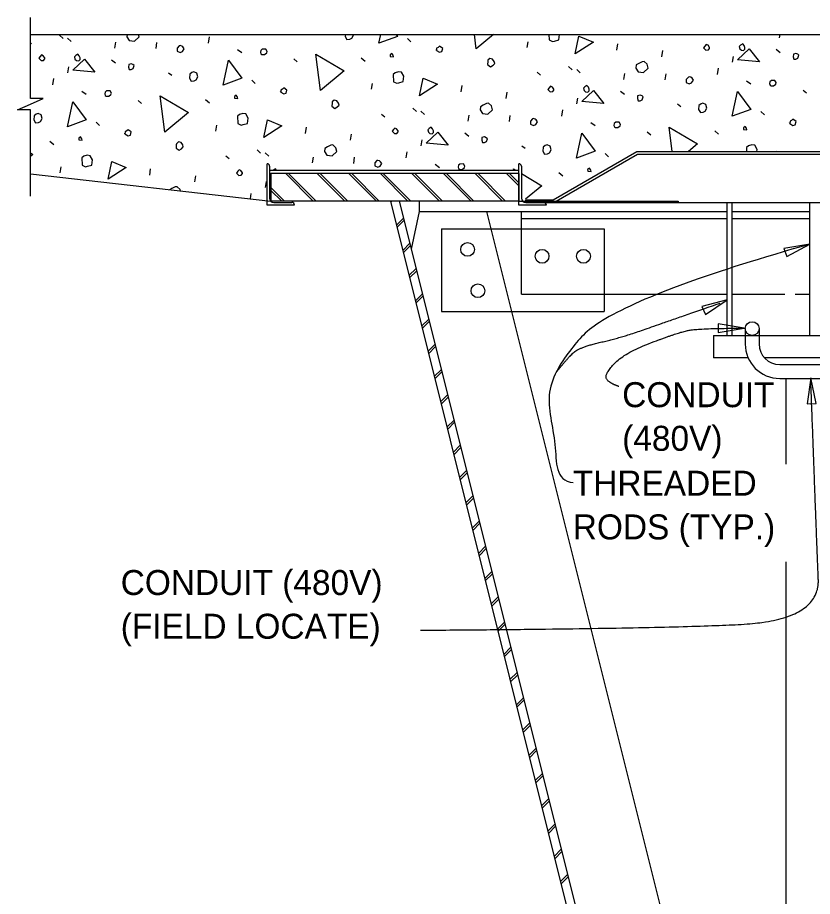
# Model space of a CAD drawing. Extents: x 927736.2 to 927809.6, y 636703.6 to 636757.7.
# Drawn here: x 927752.87 to 927764.73, y 636743.33 to 636756.45 of the extents above; entities that cross this region are included whole.
import ezdxf

# ---------------------------------------------------------------- set-up
doc = ezdxf.new("R2010")
doc.units = 0
for name, color, linetype in [('Default', 7, 'Continuous'), ('DimLines_dp', 7, 'Continuous'), ('Miscellaneous1', 7, 'Continuous'), ('Miscellaneous2', 7, 'Continuous'), ('Miscellaneous3', 7, 'Continuous')]:
    doc.layers.add(name, color=color, linetype=linetype)

msp = doc.modelspace()

# ---------------------------------------------------------------- linework, layer by layer
at = {"layer": 'Default'}
msp.add_line((927758.438, 636753.691), (927758.453, 636753.706), dxfattribs=at)
at = {"layer": 'DimLines_dp'}
msp.add_lwpolyline([(927753.063, 636753.782), (927753.063, 636755.07), (927752.871, 636755.07), (927753.063, 636755.153), (927753.254, 636755.237), (927753.063, 636755.237), (927753.063, 636756.446)], dxfattribs=at)
for points in [[(927764.692, 636753.067), (927764.306, 636753.003), (927764.349, 636752.88)], [(927763.458, 636752.234), (927763.081, 636752.133), (927763.135, 636752.014)], [(927763.711, 636751.811), (927763.325, 636751.876), (927763.325, 636751.746)], [(927764.705, 636751.071), (927764.654, 636750.684), (927764.785, 636750.688)]]:
    msp.add_lwpolyline(points, close=True, dxfattribs=at)
for points, degree in [([(927764.692, 636753.067), (927763.962, 636752.853), (927762.754, 636752.488), (927761.495, 636751.921), (927761.155, 636751.556), (927760.689, 636750.876), (927760.946, 636750.081), (927760.886, 636749.533), (927761.163, 636749.508)], 3), ([(927760.903, 636751.146), (927761.067, 636751.354), (927761.256, 636751.531), (927761.873, 636751.669), (927762.515, 636751.896), (927763.355, 636752.186)], 2), ([(927761.841, 636750.942), (927761.696, 636750.992), (927761.621, 636751.118), (927761.929, 636751.446), (927762.729, 636751.748), (927763.037, 636751.811), (927763.711, 636751.811)], 2), ([(927758.883, 636747.305), (927762.516, 636747.33), (927764.844, 636747.456), (927764.793, 636748.678), (927764.705, 636751.071)], 2)]:
    msp.add_open_spline(points, degree=degree, dxfattribs=at)
at = {"layer": 'Miscellaneous1'}
for p, q in [((927763.728, 636751.805), (927763.728, 636751.575)), ((927763.934, 636751.805), (927763.934, 636751.576)), ((927763.253, 636751.702), (927763.253, 636751.368)), ((927763.253, 636751.702), (927764.974, 636751.702)), ((927763.772, 636751.368), (927763.253, 636751.368)), ((927764.974, 636751.368), (927764.014, 636751.368)), ((927765.497, 636751.267), (927764.242, 636751.267)), ((927764.242, 636751.062), (927765.497, 636751.061))]:
    msp.add_line(p, q, dxfattribs=at)
msp.add_circle((927763.831, 636751.805), 0.103, dxfattribs=at)
for centre, radius in [((927764.242, 636751.575), 0.514), ((927764.242, 636751.576), 0.308)]:
    msp.add_arc(centre, radius, 180, 269.9792, dxfattribs=at)
at = {"layer": 'Miscellaneous2'}
for p, q in [((927753.063, 636756.193), (927774, 636756.193)), ((927753.498, 636756.185), (927753.55, 636756.135)), ((927753.618, 636756.14), (927753.67, 636756.09)), ((927755.72, 636756.065), (927755.733, 636756.158)), ((927758.689, 636756.133), (927758.741, 636756.083)), ((927764.24, 636756.145), (927764.248, 636756.193)), ((927753.063, 636756.069), (927753.08, 636756.053)), ((927754.322, 636755.991), (927754.337, 636756.078)), ((927754.937, 636755.983), (927754.951, 636756.076)), ((927760.475, 636755.998), (927760.49, 636756.085)), ((927761.813, 636755.961), (927761.826, 636756.054)), ((927756.154, 636755.971), (927756.217, 636755.924)), ((927762.485, 636755.86), (927762.498, 636755.953)), ((927764.191, 636755.973), (927764.249, 636755.924)), ((927754.273, 636755.818), (927754.331, 636755.769)), ((927756.995, 636755.832), (927757.045, 636755.788)), ((927758, 636755.846), (927758.058, 636755.798)), ((927763.54, 636755.779), (927763.555, 636755.866)), ((927753.623, 636755.624), (927753.638, 636755.711)), ((927755.123, 636755.624), (927755.171, 636755.586)), ((927760.625, 636755.63), (927760.675, 636755.586)), ((927761.093, 636755.717), (927761.144, 636755.667)), ((927761.213, 636755.673), (927761.265, 636755.623)), ((927761.917, 636755.523), (927761.932, 636755.61)), ((927762.532, 636755.515), (927762.546, 636755.608)), ((927763.315, 636755.597), (927763.328, 636755.69)), ((927753.397, 636755.443), (927753.41, 636755.535)), ((927756.366, 636755.51), (927756.418, 636755.46)), ((927763.749, 636755.503), (927763.812, 636755.456)), ((927753.831, 636755.348), (927753.894, 636755.301)), ((927758.152, 636755.376), (927758.167, 636755.463)), ((927759.49, 636755.339), (927759.503, 636755.432)), ((927761.868, 636755.35), (927761.925, 636755.302)), ((927764.59, 636755.365), (927764.64, 636755.321)), ((927755.677, 636755.224), (927755.735, 636755.175)), ((927760.161, 636755.238), (927760.175, 636755.331)), ((927761.217, 636755.157), (927761.232, 636755.244)), ((927754.672, 636755.21), (927754.722, 636755.166)), ((927758.77, 636755.095), (927758.821, 636755.045)), ((927762.718, 636755.157), (927762.766, 636755.118)), ((927758.302, 636755.007), (927758.352, 636754.963)), ((927758.89, 636755.05), (927758.942, 636755)), ((927759.594, 636754.901), (927759.609, 636754.988)), ((927760.209, 636754.893), (927760.223, 636754.986)), ((927760.992, 636754.975), (927761.005, 636755.068)), ((927763.961, 636755.043), (927764.013, 636754.993)), ((927754.043, 636754.888), (927754.095, 636754.838)), ((927755.829, 636754.753), (927755.844, 636754.84)), ((927761.425, 636754.881), (927761.489, 636754.834)), ((927757.167, 636754.716), (927757.18, 636754.809)), ((927757.838, 636754.615), (927757.852, 636754.708)), ((927759.545, 636754.728), (927759.602, 636754.679)), ((927762.267, 636754.742), (927762.317, 636754.698)), ((927763.272, 636754.756), (927763.33, 636754.708)), ((927753.354, 636754.601), (927753.412, 636754.553)), ((927758.894, 636754.534), (927758.909, 636754.621)), ((927756.447, 636754.472), (927756.498, 636754.422)), ((927756.567, 636754.428), (927756.619, 636754.378)), ((927758.669, 636754.352), (927758.682, 636754.445)), ((927760.395, 636754.534), (927760.443, 636754.496)), ((927760.864, 636753.726), (927762.11, 636754.446)), ((927762.11, 636754.446), (927774, 636754.446)), ((927755.978, 636754.385), (927756.029, 636754.341)), ((927757.271, 636754.278), (927757.286, 636754.365)), ((927757.886, 636754.27), (927757.899, 636754.363)), ((927760.874, 636753.688), (927762.121, 636754.407)), ((927761.638, 636754.42), (927761.69, 636754.37)), ((927762.121, 636754.407), (927774, 636754.407)), ((927753.506, 636754.131), (927753.521, 636754.218)), ((927754.844, 636754.094), (927754.857, 636754.187)), ((927756.593, 636753.649), (927756.593, 636754.266)), ((927756.631, 636754.227), (927756.631, 636753.752)), ((927756.631, 636754.169), (927760.35, 636754.169)), ((927759.102, 636754.258), (927759.166, 636754.211)), ((927760.35, 636753.649), (927760.35, 636754.266)), ((927760.389, 636754.227), (927760.389, 636753.752)), ((927753.063, 636754.114), (927756.65, 636753.706)), ((927755.515, 636753.993), (927755.529, 636754.086)), ((927756.631, 636754.118), (927756.65, 636754.118)), ((927757.283, 636753.706), (927756.872, 636754.118)), ((927757.326, 636753.706), (927756.915, 636754.118)), ((927757.754, 636753.706), (927757.343, 636754.118)), ((927757.797, 636753.706), (927757.386, 636754.118)), ((927758.225, 636753.706), (927757.813, 636754.118)), ((927758.268, 636753.706), (927757.857, 636754.118)), ((927758.696, 636753.706), (927758.284, 636754.118)), ((927758.739, 636753.706), (927758.328, 636754.118)), ((927759.167, 636753.706), (927758.755, 636754.118)), ((927759.21, 636753.706), (927758.799, 636754.118)), ((927759.638, 636753.706), (927759.226, 636754.118)), ((927759.681, 636753.706), (927759.27, 636754.118)), ((927760.108, 636753.706), (927759.697, 636754.118)), ((927760.152, 636753.706), (927759.741, 636754.118)), ((927760.35, 636753.936), (927760.168, 636754.118)), ((927760.35, 636753.979), (927760.212, 636754.118)), ((927760.35, 636754.118), (927760.35, 636753.706)), ((927760.949, 636754.134), (927761.007, 636754.085)), ((927756.571, 636753.912), (927756.586, 636753.999)), ((927756.856, 636753.706), (927756.65, 636753.912)), ((927756.347, 636753.741), (927756.359, 636753.823)), ((927756.812, 636753.706), (927756.65, 636753.868)), ((927757.004, 636753.649), (927756.593, 636753.649)), ((927756.695, 636753.688), (927756.965, 636753.688)), ((927760.344, 636753.706), (927760.35, 636753.713)), ((927760.344, 636753.706), (927760.35, 636753.713)), ((927760.761, 636753.649), (927760.35, 636753.649)), ((927760.453, 636753.726), (927760.864, 636753.726)), ((927760.453, 636753.688), (927760.453, 636753.726)), ((927760.453, 636753.688), (927760.723, 636753.688)), ((927760.453, 636753.688), (927774, 636753.688))]:
    msp.add_line(p, q, dxfattribs=at)
for points in [[(927754.501, 636756.16), (927754.534, 636756.105), (927754.614, 636756.094), (927754.686, 636756.158), (927754.677, 636756.193)], [(927754.505, 636756.193), (927754.501, 636756.16)], [(927757.763, 636756.193), (927757.761, 636756.165), (927757.786, 636756.121), (927757.829, 636756.126), (927757.858, 636756.14), (927757.884, 636756.185), (927757.882, 636756.193)], [(927758.261, 636756.063), (927758.289, 636756.193)], [(927758.519, 636756.193), (927758.541, 636756.163), (927758.261, 636756.063)], [(927759.714, 636755.98), (927759.687, 636756.193)], [(927759.972, 636756.193), (927759.714, 636755.98)], [(927760.799, 636756.193), (927760.802, 636756.112), (927760.853, 636756.087), (927760.883, 636756.095), (927760.949, 636756.113), (927760.959, 636756.192), (927760.959, 636756.193)], [(927761.19, 636755.903), (927761.247, 636756.167), (927761.462, 636756.078), (927761.19, 636755.903)], [(927755.254, 636755.991), (927755.254, 636755.946), (927755.297, 636755.926), (927755.331, 636755.942), (927755.359, 636755.981), (927755.339, 636756.008), (927755.323, 636756.022), (927755.296, 636756.028), (927755.284, 636756.025), (927755.254, 636755.991)], [(927759.12, 636755.955), (927759.166, 636755.928), (927759.201, 636755.938), (927759.214, 636755.986), (927759.167, 636756.018), (927759.146, 636756), (927759.124, 636755.988), (927759.12, 636755.955), (927759.117, 636755.967)], [(927763.106, 636755.995), (927763.141, 636755.959), (927763.178, 636755.963), (927763.197, 636755.987), (927763.194, 636755.999), (927763.173, 636756.032), (927763.144, 636756.043), (927763.125, 636756.019), (927763.106, 636755.995)], [(927763.646, 636755.98), (927763.671, 636755.961), (927763.703, 636755.957), (927763.724, 636755.975), (927763.724, 636756.001), (927763.71, 636756.029), (927763.69, 636756.055), (927763.657, 636756.034), (927763.637, 636756.016), (927763.646, 636755.98)], [(927753.188, 636755.84), (927753.223, 636755.805), (927753.26, 636755.808), (927753.28, 636755.832), (927753.276, 636755.844), (927753.255, 636755.877), (927753.226, 636755.888), (927753.207, 636755.864), (927753.188, 636755.84)], [(927753.728, 636755.825), (927753.753, 636755.806), (927753.786, 636755.802), (927753.806, 636755.82), (927753.806, 636755.846), (927753.792, 636755.874), (927753.772, 636755.901), (927753.739, 636755.879), (927753.719, 636755.861), (927753.728, 636755.825)], [(927756.503, 636755.905), (927756.518, 636755.896), (927756.557, 636755.894), (927756.588, 636755.921), (927756.595, 636755.942), (927756.574, 636755.975), (927756.523, 636755.974), (927756.503, 636755.955), (927756.497, 636755.928), (927756.503, 636755.905)], [(927757.391, 636755.357), (927757.322, 636755.9), (927757.746, 636755.65), (927757.391, 636755.357)], [(927758.429, 636755.865), (927758.482, 636755.86), (927758.475, 636755.884), (927758.455, 636755.911), (927758.429, 636755.891), (927758.429, 636755.865)], [(927763.613, 636755.818), (927763.787, 636755.979), (927763.941, 636755.784), (927763.613, 636755.818)], [(927764.444, 636755.862), (927764.454, 636755.826), (927764.485, 636755.828), (927764.513, 636755.842), (927764.527, 636755.884), (927764.511, 636755.899), (927764.482, 636755.91), (927764.446, 636755.901), (927764.444, 636755.862)], [(927753.695, 636755.663), (927753.869, 636755.824), (927754.023, 636755.63), (927753.695, 636755.663)], [(927754.526, 636755.707), (927754.536, 636755.671), (927754.567, 636755.673), (927754.595, 636755.687), (927754.61, 636755.729), (927754.593, 636755.744), (927754.564, 636755.755), (927754.529, 636755.746), (927754.526, 636755.707)], [(927755.938, 636755.44), (927756.017, 636755.813), (927756.218, 636755.541), (927755.938, 636755.44)], [(927759.886, 636755.79), (927759.885, 636755.745), (927759.926, 636755.711), (927759.965, 636755.734), (927759.99, 636755.76), (927759.982, 636755.79), (927759.959, 636755.828), (927759.918, 636755.836), (927759.887, 636755.809), (927759.886, 636755.79)], [(927762.095, 636755.692), (927762.129, 636755.637), (927762.209, 636755.627), (927762.281, 636755.691), (927762.265, 636755.75), (927762.222, 636755.79), (927762.191, 636755.788), (927762.141, 636755.762), (927762.102, 636755.739), (927762.095, 636755.692)], [(927755.442, 636755.601), (927755.438, 636755.543), (927755.463, 636755.498), (927755.506, 636755.503), (927755.535, 636755.517), (927755.561, 636755.563), (927755.546, 636755.616), (927755.503, 636755.637), (927755.473, 636755.629), (927755.442, 636755.601)], [(927758.476, 636755.597), (927758.479, 636755.489), (927758.53, 636755.465), (927758.56, 636755.473), (927758.625, 636755.49), (927758.636, 636755.57), (927758.601, 636755.63), (927758.554, 636755.637), (927758.507, 636755.624), (927758.476, 636755.597)], [(927758.867, 636755.28), (927758.924, 636755.544), (927759.139, 636755.455), (927758.867, 636755.28)], [(927762.849, 636755.524), (927762.848, 636755.479), (927762.892, 636755.459), (927762.926, 636755.474), (927762.954, 636755.514), (927762.934, 636755.54), (927762.917, 636755.555), (927762.89, 636755.56), (927762.879, 636755.557), (927762.849, 636755.524)], [(927764.098, 636755.437), (927764.113, 636755.428), (927764.152, 636755.426), (927764.183, 636755.453), (927764.19, 636755.475), (927764.169, 636755.507), (927764.118, 636755.506), (927764.097, 636755.488), (927764.092, 636755.461), (927764.098, 636755.437)], [(927754.18, 636755.282), (927754.195, 636755.273), (927754.234, 636755.271), (927754.265, 636755.299), (927754.272, 636755.32), (927754.251, 636755.352), (927754.2, 636755.351), (927754.179, 636755.333), (927754.174, 636755.306), (927754.18, 636755.282)], [(927756.797, 636755.332), (927756.843, 636755.306), (927756.878, 636755.316), (927756.891, 636755.364), (927756.844, 636755.396), (927756.823, 636755.377), (927756.801, 636755.365), (927756.797, 636755.332), (927756.794, 636755.344)], [(927760.783, 636755.372), (927760.818, 636755.337), (927760.855, 636755.341), (927760.874, 636755.365), (927760.871, 636755.377), (927760.85, 636755.409), (927760.821, 636755.421), (927760.802, 636755.397), (927760.783, 636755.372)], [(927761.29, 636755.195), (927761.464, 636755.357), (927761.618, 636755.162), (927761.29, 636755.195)], [(927761.323, 636755.357), (927761.347, 636755.338), (927761.38, 636755.334), (927761.401, 636755.353), (927761.401, 636755.378), (927761.387, 636755.406), (927761.367, 636755.433), (927761.334, 636755.411), (927761.314, 636755.393), (927761.323, 636755.357)], [(927755.068, 636754.735), (927754.999, 636755.278), (927755.423, 636755.028), (927755.068, 636754.735)], [(927756.106, 636755.243), (927756.159, 636755.238), (927756.152, 636755.261), (927756.132, 636755.288), (927756.106, 636755.268), (927756.106, 636755.243)], [(927762.121, 636755.239), (927762.131, 636755.204), (927762.162, 636755.206), (927762.19, 636755.219), (927762.204, 636755.262), (927762.188, 636755.276), (927762.159, 636755.288), (927762.123, 636755.278), (927762.121, 636755.239)], [(927763.533, 636754.973), (927763.612, 636755.345), (927763.813, 636755.073), (927763.533, 636754.973)], [(927753.615, 636754.818), (927753.694, 636755.19), (927753.895, 636754.918), (927753.615, 636754.818)], [(927757.563, 636755.167), (927757.562, 636755.122), (927757.603, 636755.088), (927757.642, 636755.112), (927757.667, 636755.137), (927757.659, 636755.167), (927757.636, 636755.206), (927757.595, 636755.214), (927757.564, 636755.187), (927757.563, 636755.167)], [(927759.772, 636755.07), (927759.806, 636755.015), (927759.886, 636755.004), (927759.958, 636755.068), (927759.942, 636755.128), (927759.899, 636755.167), (927759.868, 636755.165), (927759.818, 636755.139), (927759.779, 636755.116), (927759.772, 636755.07)], [(927763.037, 636755.133), (927763.033, 636755.075), (927763.058, 636755.031), (927763.101, 636755.036), (927763.129, 636755.05), (927763.156, 636755.095), (927763.141, 636755.149), (927763.097, 636755.169), (927763.068, 636755.161), (927763.037, 636755.133)], [(927753.119, 636754.979), (927753.115, 636754.92), (927753.14, 636754.876), (927753.183, 636754.881), (927753.212, 636754.895), (927753.238, 636754.94), (927753.223, 636754.994), (927753.18, 636755.014), (927753.15, 636755.006), (927753.119, 636754.979)], [(927756.153, 636754.974), (927756.156, 636754.867), (927756.207, 636754.842), (927756.237, 636754.85), (927756.302, 636754.868), (927756.313, 636754.947), (927756.278, 636755.008), (927756.231, 636755.015), (927756.183, 636755.002), (927756.153, 636754.974)], [(927756.544, 636754.658), (927756.601, 636754.922), (927756.816, 636754.833), (927756.544, 636754.658)], [(927760.526, 636754.901), (927760.525, 636754.856), (927760.569, 636754.836), (927760.603, 636754.852), (927760.631, 636754.891), (927760.611, 636754.918), (927760.594, 636754.932), (927760.567, 636754.938), (927760.555, 636754.935), (927760.526, 636754.901)], [(927761.775, 636754.815), (927761.79, 636754.806), (927761.829, 636754.804), (927761.86, 636754.831), (927761.867, 636754.852), (927761.846, 636754.885), (927761.795, 636754.884), (927761.774, 636754.865), (927761.769, 636754.838), (927761.775, 636754.815)], [(927764.392, 636754.865), (927764.437, 636754.838), (927764.473, 636754.848), (927764.486, 636754.896), (927764.439, 636754.928), (927764.418, 636754.91), (927764.396, 636754.898), (927764.392, 636754.865), (927764.389, 636754.877)], [(927754.474, 636754.71), (927754.519, 636754.684), (927754.555, 636754.693), (927754.568, 636754.741), (927754.521, 636754.773), (927754.5, 636754.755), (927754.478, 636754.743), (927754.474, 636754.71), (927754.471, 636754.722)], [(927758.46, 636754.75), (927758.495, 636754.715), (927758.532, 636754.718), (927758.551, 636754.742), (927758.548, 636754.754), (927758.527, 636754.787), (927758.498, 636754.798), (927758.479, 636754.774), (927758.46, 636754.75)], [(927758.967, 636754.573), (927759.141, 636754.734), (927759.295, 636754.54), (927758.967, 636754.573)], [(927759, 636754.735), (927759.024, 636754.716), (927759.057, 636754.712), (927759.078, 636754.73), (927759.078, 636754.756), (927759.064, 636754.784), (927759.044, 636754.811), (927759.011, 636754.789), (927758.991, 636754.771), (927759, 636754.735)], [(927761.21, 636754.35), (927761.289, 636754.723), (927761.49, 636754.451), (927761.21, 636754.35)], [(927762.64, 636754.446), (927762.593, 636754.81), (927763.018, 636754.56), (927762.879, 636754.446)], [(927763.701, 636754.775), (927763.753, 636754.77), (927763.747, 636754.794), (927763.727, 636754.821), (927763.701, 636754.801), (927763.701, 636754.775)], [(927753.783, 636754.62), (927753.836, 636754.615), (927753.829, 636754.639), (927753.809, 636754.666), (927753.783, 636754.646), (927753.783, 636754.62)], [(927755.24, 636754.545), (927755.239, 636754.5), (927755.28, 636754.466), (927755.319, 636754.489), (927755.344, 636754.515), (927755.336, 636754.545), (927755.312, 636754.583), (927755.272, 636754.592), (927755.241, 636754.564), (927755.24, 636754.545)], [(927759.798, 636754.617), (927759.808, 636754.581), (927759.839, 636754.583), (927759.867, 636754.597), (927759.881, 636754.639), (927759.865, 636754.654), (927759.836, 636754.665), (927759.8, 636754.656), (927759.798, 636754.617)], [(927753.063, 636754.427), (927753.1, 636754.405), (927753.063, 636754.374)], [(927757.449, 636754.447), (927757.483, 636754.392), (927757.563, 636754.382), (927757.635, 636754.446), (927757.619, 636754.505), (927757.576, 636754.545), (927757.545, 636754.543), (927757.495, 636754.517), (927757.456, 636754.494), (927757.449, 636754.447)], [(927760.714, 636754.511), (927760.71, 636754.453), (927760.735, 636754.408), (927760.778, 636754.413), (927760.806, 636754.427), (927760.833, 636754.473), (927760.818, 636754.526), (927760.774, 636754.546), (927760.745, 636754.538), (927760.714, 636754.511)], [(927763.903, 636754.446), (927763.908, 636754.479), (927763.872, 636754.54), (927763.826, 636754.547), (927763.778, 636754.534), (927763.747, 636754.507)], [(927763.747, 636754.507), (927763.749, 636754.446)], [(927764.194, 636754.446), (927764.195, 636754.454), (927764.216, 636754.446)], [(927753.829, 636754.352), (927753.833, 636754.244), (927753.884, 636754.22), (927753.914, 636754.228), (927753.979, 636754.245), (927753.99, 636754.325), (927753.955, 636754.385), (927753.908, 636754.392), (927753.86, 636754.379), (927753.829, 636754.352)], [(927754.221, 636754.035), (927754.278, 636754.3), (927754.493, 636754.21), (927754.221, 636754.035)], [(927758.203, 636754.279), (927758.202, 636754.234), (927758.246, 636754.214), (927758.28, 636754.229), (927758.308, 636754.269), (927758.288, 636754.295), (927758.271, 636754.31), (927758.244, 636754.315), (927758.232, 636754.312), (927758.203, 636754.279)], [(927756.137, 636754.127), (927756.172, 636754.092), (927756.209, 636754.096), (927756.228, 636754.12), (927756.225, 636754.132), (927756.204, 636754.164), (927756.175, 636754.176), (927756.156, 636754.152), (927756.137, 636754.127)], [(927756.735, 636754.169), (927756.721, 636754.188), (927756.692, 636754.169)], [(927759.452, 636754.192), (927759.467, 636754.183), (927759.506, 636754.181), (927759.537, 636754.209), (927759.544, 636754.23), (927759.523, 636754.262), (927759.472, 636754.261), (927759.451, 636754.243), (927759.446, 636754.216), (927759.452, 636754.192)], [(927760.273, 636754.169), (927760.27, 636754.188), (927760.303, 636754.169)], [(927761.378, 636754.153), (927761.43, 636754.148), (927761.424, 636754.171), (927761.404, 636754.198), (927761.377, 636754.178), (927761.378, 636754.153)], [(927760.389, 636754.118), (927760.695, 636753.938), (927760.451, 636753.736)], [(927755.302, 636753.86), (927755.296, 636753.883), (927755.253, 636753.923), (927755.222, 636753.921), (927755.171, 636753.894), (927755.144, 636753.878)]]:
    msp.add_lwpolyline(points, dxfattribs=at)
for centre, radius, start, end in [((927756.593, 636754.227), 0.0385, 359.9953, 89.9953), ((927760.35, 636754.227), 0.0385, 359.9953, 89.9953), ((927756.695, 636753.752), 0.0642, 179.9953, 269.9953), ((927756.965, 636753.649), 0.0385, 359.9953, 89.9953), ((927760.453, 636753.752), 0.0642, 179.9953, 269.9953), ((927760.723, 636753.649), 0.0385, 359.9953, 89.9953)]:
    msp.add_arc(centre, radius, start, end, dxfattribs=at)
at = {"layer": 'Miscellaneous3'}
for p, q in [((927760.35, 636754.118), (927756.65, 636754.118)), ((927756.65, 636754.118), (927756.65, 636753.706)), ((927760.35, 636753.706), (927756.65, 636753.706)), ((927758.434, 636753.706), (927762.288, 636738.29)), ((927758.566, 636753.706), (927762.42, 636738.29)), ((927758.867, 636753.552), (927758.867, 636753.706)), ((927760.35, 636753.706), (927762.729, 636753.706)), ((927762.729, 636753.706), (927762.729, 636753.688)), ((927763.458, 636751.702), (927763.458, 636753.688)), ((927763.535, 636751.702), (927763.535, 636753.688)), ((927764.692, 636751.702), (927764.692, 636753.688)), ((927758.862, 636753.552), (927758.745, 636752.99)), ((927758.867, 636753.552), (927763.458, 636753.552)), ((927759.868, 636753.552), (927759.933, 636753.295)), ((927760.389, 636753.269), (927760.389, 636753.552)), ((927763.535, 636753.552), (927764.692, 636753.552)), ((927758.523, 636753.349), (927758.629, 636753.455)), ((927758.532, 636753.315), (927758.638, 636753.421)), ((927760.389, 636752.319), (927760.389, 636753.449)), ((927760.389, 636753.449), (927763.458, 636753.449)), ((927763.535, 636753.449), (927764.692, 636753.449)), ((927759.194, 636753.295), (927759.194, 636752.062)), ((927759.194, 636753.295), (927761.622, 636753.295)), ((927759.933, 636753.295), (927760.241, 636752.062)), ((927761.622, 636753.295), (927761.622, 636752.062)), ((927758.617, 636752.973), (927758.723, 636753.079)), ((927758.626, 636752.938), (927758.732, 636753.044)), ((927758.711, 636752.596), (927758.817, 636752.702)), ((927758.72, 636752.561), (927758.826, 636752.667)), ((927758.806, 636752.219), (927758.912, 636752.325)), ((927758.814, 636752.184), (927758.92, 636752.29)), ((927760.389, 636752.319), (927761.622, 636752.319)), ((927761.622, 636752.319), (927763.458, 636752.319)), ((927763.535, 636752.319), (927764.319, 636752.319)), ((927764.473, 636752.319), (927764.692, 636752.319)), ((927758.9, 636751.842), (927759.006, 636751.948)), ((927759.194, 636752.062), (927761.622, 636752.062)), ((927760.241, 636752.062), (927762.676, 636742.324)), ((927758.909, 636751.808), (927759.015, 636751.914)), ((927758.994, 636751.466), (927759.1, 636751.572)), ((927759.003, 636751.431), (927759.109, 636751.537)), ((927759.088, 636751.089), (927759.194, 636751.195)), ((927759.097, 636751.054), (927759.203, 636751.16)), ((927759.182, 636750.712), (927759.288, 636750.818)), ((927759.191, 636750.677), (927759.297, 636750.783)), ((927759.277, 636750.335), (927759.383, 636750.441)), ((927759.285, 636750.301), (927759.391, 636750.407)), ((927759.371, 636749.959), (927759.477, 636750.065)), ((927759.379, 636749.924), (927759.485, 636750.03)), ((927759.465, 636749.582), (927759.571, 636749.688)), ((927759.474, 636749.547), (927759.58, 636749.653)), ((927759.559, 636749.205), (927759.665, 636749.311)), ((927759.568, 636749.17), (927759.674, 636749.276)), ((927759.653, 636748.829), (927759.759, 636748.934)), ((927759.662, 636748.794), (927759.768, 636748.9)), ((927759.748, 636748.452), (927759.853, 636748.558)), ((927759.756, 636748.417), (927759.862, 636748.523)), ((927759.842, 636748.075), (927759.948, 636748.181)), ((927759.85, 636748.04), (927759.956, 636748.146)), ((927759.936, 636747.698), (927760.042, 636747.804)), ((927759.945, 636747.663), (927760.051, 636747.769)), ((927760.03, 636747.322), (927760.136, 636747.427)), ((927760.039, 636747.287), (927760.145, 636747.393)), ((927760.124, 636746.945), (927760.23, 636747.051)), ((927760.133, 636746.91), (927760.239, 636747.016)), ((927760.218, 636746.568), (927760.324, 636746.674)), ((927760.227, 636746.533), (927760.333, 636746.639)), ((927760.313, 636746.191), (927760.419, 636746.297)), ((927760.321, 636746.156), (927760.427, 636746.262)), ((927760.407, 636745.815), (927760.513, 636745.921)), ((927760.416, 636745.78), (927760.522, 636745.886)), ((927760.501, 636745.438), (927760.607, 636745.544)), ((927760.51, 636745.403), (927760.616, 636745.509)), ((927760.595, 636745.061), (927760.701, 636745.167)), ((927760.604, 636745.026), (927760.71, 636745.132)), ((927760.689, 636744.684), (927760.795, 636744.79)), ((927760.698, 636744.649), (927760.804, 636744.755)), ((927760.784, 636744.308), (927760.89, 636744.414)), ((927760.792, 636744.273), (927760.898, 636744.379)), ((927760.878, 636743.931), (927760.984, 636744.037)), ((927760.886, 636743.896), (927760.992, 636744.002)), ((927760.972, 636743.554), (927761.078, 636743.66)), ((927760.981, 636743.519), (927761.087, 636743.625))]:
    msp.add_line(p, q, dxfattribs=at)
for points in [[(927764.332, 636751.062), (927764.332, 636749.785)], [(927764.332, 636748.324), (927764.332, 636743.124), (927766.449, 636743.124)]]:
    msp.add_lwpolyline(points, dxfattribs=at)
for centre in [(927759.586, 636752.987), (927760.697, 636752.884), (927761.314, 636752.884), (927759.74, 636752.37)]:
    msp.add_circle(centre, 0.103, dxfattribs=at)

# ---------------------------------------------------------------- texts
at = {"layer": 'DimLines_dp'}
for s, height, p in [('CONDUIT', 0.373, (927761.892, 636750.633)), ('(480V)', 0.373, (927761.892, 636749.982)), ('THREADED', 0.373, (927761.155, 636749.312)), ('RODS (TYP.)', 0.37296, (927761.155, 636748.66)), ('CONDUIT (480V)', 0.37296, (927754.41, 636747.83)), ('(FIELD LOCATE)', 0.37296, (927754.41, 636747.178))]:
    msp.add_text(s, height=height, dxfattribs=at).set_placement(p)

doc.saveas('drawing.dxf')
